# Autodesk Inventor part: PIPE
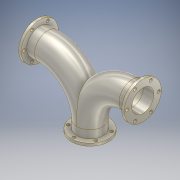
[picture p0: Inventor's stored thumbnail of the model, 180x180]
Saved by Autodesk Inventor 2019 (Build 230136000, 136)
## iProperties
Created: 2018-02
Part Number: PIPE
Material: Titanium
Document SubType Name: Modeling
Designer: User
Density: 4.51 g/cm^3
Appearance: Titanium
Mass: 792.799 g
Surface Area: 896.672 cm^2
Volume: 175.787 cm^3
Author: User
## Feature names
1. Extrusion1
2. Sweep1
3. Extrusion2
4. Mirror1
5. Sweep2
6. Mirror2
## Parameters: d3 = 6 mm, d4 = 42 mm, d7 = 360 deg, d9 = 5 mm, d10 = 0, d13 = 2 mm, d15 = 0, d16 = 0, d22 = 6 mm, d23 = 42 mm, d24 = 360 deg, d25 = 5 mm, d26 = 0, d27 = 0, d28 = 0
